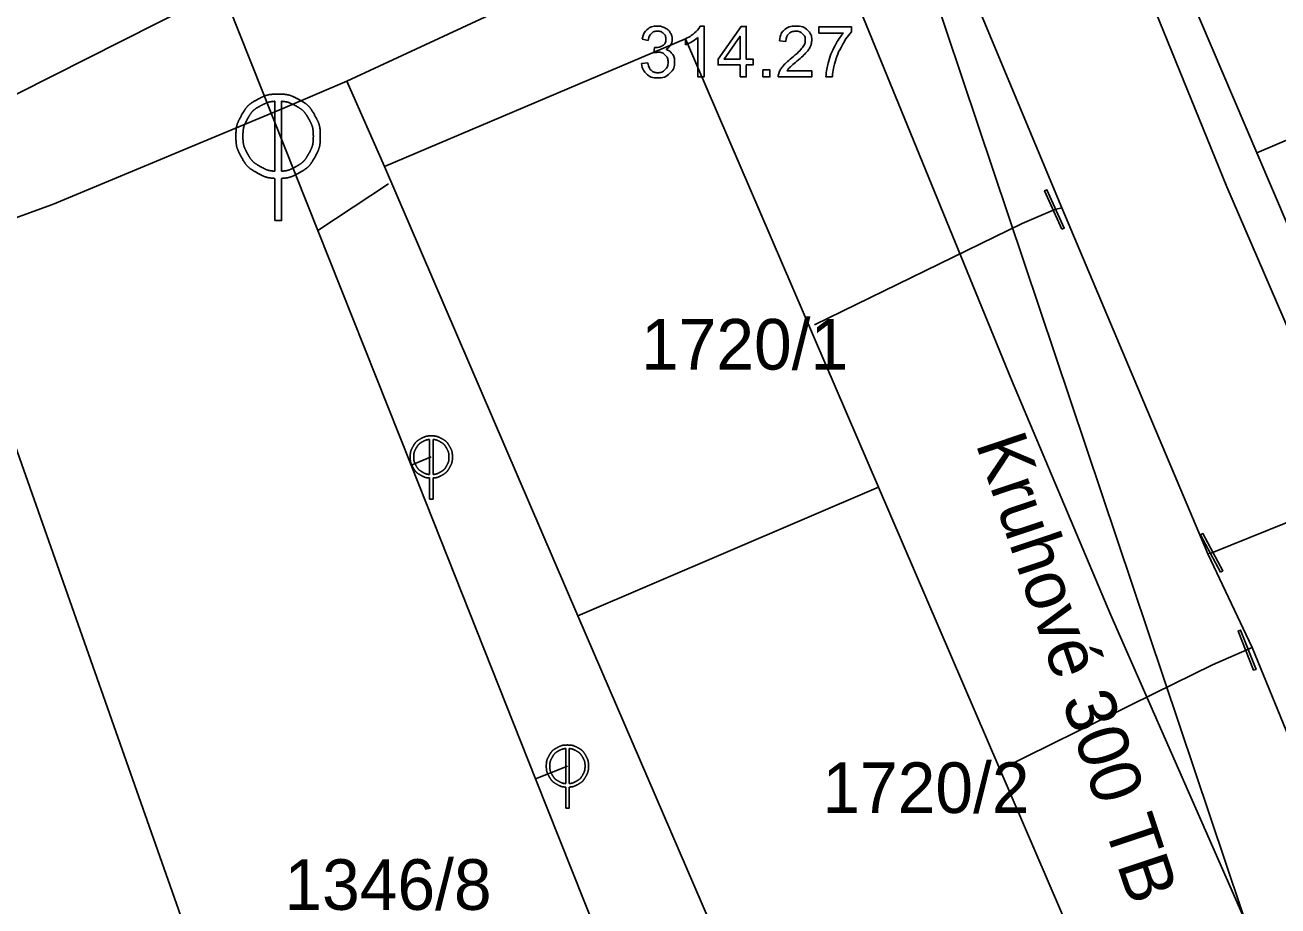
# Model space of a CAD drawing. Extents: x -562248 to -562040, y -1079385 to -1079027.
# Drawn here: x -562124.4 to -562087.3, y -1079242.75 to -1079216.65 of the extents above; entities that cross this region are included whole.
import ezdxf

# ---------------------------------------------------------------- set-up
doc = ezdxf.new("R2010")
doc.units = 0
for name, color, linetype in [('Armatura vodovodní', 7, 'Continuous'), ('Default', 7, 'Continuous'), ('Kanalizační přípojka', 7, 'Continuous'), ('Kanalizační stoka', 7, 'Continuous'), ('Kanalizační šachta', 7, 'Continuous'), ('Parcela-polygon', 7, 'Continuous'), ('Parcela-text', 7, 'Continuous'), ('Popis kmenové stoky', 7, 'Continuous'), ('Popis šachty', 7, 'Continuous'), ('Vodovodní přípojka', 7, 'Continuous'), ('Vodovodní řad', 7, 'Continuous')]:
    doc.layers.add(name, color=color, linetype=linetype)

msp = doc.modelspace()

# ---------------------------------------------------------------- linework, layer by layer
at = {"layer": 'Armatura vodovodní'}
for points in [[(-562093.697, -1079222.7), (-562093.626, -1079222.668), (-562094.14, -1079221.529), (-562094.211, -1079221.561)], [(-562088.996, -1079232.86), (-562088.927, -1079232.822), (-562089.519, -1079231.722), (-562089.588, -1079231.759)], [(-562088.018, -1079235.772), (-562087.946, -1079235.744), (-562088.405, -1079234.581), (-562088.478, -1079234.61)]]:
    msp.add_lwpolyline(points, close=True, dxfattribs=at)
at = {"layer": 'Default'}
for points in [[(-562116.907, -1079218.696), (-562117.118, -1079218.696), (-562117.323, -1079218.75), (-562117.522, -1079218.857)], [(-562116.293, -1079218.857), (-562116.492, -1079218.75), (-562116.697, -1079218.696), (-562116.907, -1079218.696)], [(-562117.522, -1079218.857), (-562117.72, -1079218.965), (-562117.876, -1079219.119), (-562117.988, -1079219.319)], [(-562117.81, -1079219.425), (-562117.717, -1079219.258), (-562117.588, -1079219.13), (-562117.422, -1079219.041)], [(-562117.422, -1079219.041), (-562117.278, -1079218.964), (-562117.141, -1079218.92), (-562117.009, -1079218.909)], [(-562116.804, -1079218.909), (-562116.672, -1079218.92), (-562116.535, -1079218.964), (-562116.394, -1079219.041)], [(-562116.394, -1079219.041), (-562116.228, -1079219.13), (-562116.098, -1079219.258), (-562116.004, -1079219.425)], [(-562115.825, -1079219.319), (-562115.937, -1079219.119), (-562116.093, -1079218.965), (-562116.293, -1079218.857)], [(-562117.988, -1079219.319), (-562118.1, -1079219.519), (-562118.157, -1079219.728), (-562118.157, -1079219.946)], [(-562117.949, -1079219.946), (-562117.949, -1079219.766), (-562117.903, -1079219.592), (-562117.81, -1079219.425)], [(-562116.004, -1079219.425), (-562115.911, -1079219.592), (-562115.864, -1079219.766), (-562115.864, -1079219.946)], [(-562115.657, -1079219.946), (-562115.657, -1079219.728), (-562115.713, -1079219.519), (-562115.825, -1079219.319)], [(-562118.157, -1079219.946), (-562118.157, -1079220.163), (-562118.102, -1079220.37), (-562117.992, -1079220.569)], [(-562117.812, -1079220.464), (-562117.903, -1079220.299), (-562117.949, -1079220.127), (-562117.949, -1079219.946)], [(-562115.864, -1079219.946), (-562115.864, -1079220.127), (-562115.91, -1079220.299), (-562116.001, -1079220.464)], [(-562115.821, -1079220.569), (-562115.711, -1079220.37), (-562115.657, -1079220.163), (-562115.657, -1079219.946)], [(-562117.427, -1079220.847), (-562117.593, -1079220.756), (-562117.721, -1079220.628), (-562117.812, -1079220.464)], [(-562116.001, -1079220.464), (-562116.092, -1079220.628), (-562116.22, -1079220.756), (-562116.384, -1079220.847)], [(-562117.992, -1079220.569), (-562117.882, -1079220.767), (-562117.728, -1079220.921), (-562117.529, -1079221.03)], [(-562117.009, -1079220.981), (-562117.146, -1079220.972), (-562117.285, -1079220.927), (-562117.427, -1079220.847)], [(-562116.384, -1079220.847), (-562116.527, -1079220.927), (-562116.667, -1079220.972), (-562116.804, -1079220.981)], [(-562116.284, -1079221.03), (-562116.085, -1079220.921), (-562115.931, -1079220.767), (-562115.821, -1079220.569)], [(-562117.529, -1079221.03), (-562117.355, -1079221.128), (-562117.182, -1079221.182), (-562117.009, -1079221.194)], [(-562116.804, -1079221.194), (-562116.631, -1079221.182), (-562116.458, -1079221.128), (-562116.284, -1079221.03)], [(-562112.678, -1079228.906), (-562112.777, -1079228.959), (-562112.855, -1079229.036), (-562112.911, -1079229.136)], [(-562112.82, -1079229.189), (-562112.774, -1079229.106), (-562112.709, -1079229.041), (-562112.626, -1079228.996)], [(-562112.37, -1079228.825), (-562112.476, -1079228.825), (-562112.578, -1079228.852), (-562112.678, -1079228.906)], [(-562112.626, -1079228.996), (-562112.555, -1079228.958), (-562112.486, -1079228.936), (-562112.421, -1079228.93)], [(-562112.062, -1079228.906), (-562112.162, -1079228.852), (-562112.264, -1079228.825), (-562112.37, -1079228.825)], [(-562112.319, -1079228.93), (-562112.252, -1079228.936), (-562112.184, -1079228.958), (-562112.114, -1079228.996)], [(-562112.114, -1079228.996), (-562112.031, -1079229.041), (-562111.966, -1079229.106), (-562111.918, -1079229.189)], [(-562111.829, -1079229.136), (-562111.885, -1079229.036), (-562111.963, -1079228.959), (-562112.062, -1079228.906)], [(-562112.911, -1079229.136), (-562112.967, -1079229.236), (-562112.995, -1079229.341), (-562112.995, -1079229.45)], [(-562112.995, -1079229.45), (-562112.995, -1079229.557), (-562112.967, -1079229.661), (-562112.912, -1079229.76)], [(-562112.89, -1079229.45), (-562112.89, -1079229.359), (-562112.867, -1079229.272), (-562112.82, -1079229.189)], [(-562112.822, -1079229.708), (-562112.867, -1079229.625), (-562112.89, -1079229.54), (-562112.89, -1079229.45)], [(-562111.918, -1079229.189), (-562111.871, -1079229.272), (-562111.848, -1079229.359), (-562111.848, -1079229.45)], [(-562111.848, -1079229.45), (-562111.848, -1079229.54), (-562111.87, -1079229.625), (-562111.916, -1079229.708)], [(-562111.745, -1079229.45), (-562111.745, -1079229.341), (-562111.773, -1079229.236), (-562111.829, -1079229.136)], [(-562111.827, -1079229.76), (-562111.772, -1079229.661), (-562111.745, -1079229.557), (-562111.745, -1079229.45)], [(-562112.912, -1079229.76), (-562112.857, -1079229.859), (-562112.779, -1079229.937), (-562112.68, -1079229.992)], [(-562112.629, -1079229.899), (-562112.712, -1079229.854), (-562112.776, -1079229.79), (-562112.822, -1079229.708)], [(-562111.916, -1079229.708), (-562111.961, -1079229.79), (-562112.026, -1079229.854), (-562112.109, -1079229.899)], [(-562112.058, -1079229.992), (-562111.958, -1079229.937), (-562111.881, -1079229.859), (-562111.827, -1079229.76)], [(-562112.68, -1079229.992), (-562112.594, -1079230.041), (-562112.508, -1079230.068), (-562112.421, -1079230.073)], [(-562112.421, -1079229.968), (-562112.49, -1079229.963), (-562112.559, -1079229.94), (-562112.629, -1079229.899)], [(-562112.109, -1079229.899), (-562112.18, -1079229.94), (-562112.25, -1079229.963), (-562112.319, -1079229.968)], [(-562112.319, -1079230.073), (-562112.232, -1079230.068), (-562112.145, -1079230.041), (-562112.058, -1079229.992)], [(-562108.34, -1079237.985), (-562108.446, -1079237.985), (-562108.548, -1079238.012), (-562108.648, -1079238.066)], [(-562108.032, -1079238.066), (-562108.132, -1079238.012), (-562108.234, -1079237.985), (-562108.34, -1079237.985)], [(-562108.881, -1079238.296), (-562108.937, -1079238.396), (-562108.965, -1079238.501), (-562108.965, -1079238.61)], [(-562108.648, -1079238.066), (-562108.747, -1079238.119), (-562108.825, -1079238.196), (-562108.881, -1079238.296)], [(-562108.86, -1079238.61), (-562108.86, -1079238.519), (-562108.837, -1079238.432), (-562108.79, -1079238.349)], [(-562108.79, -1079238.349), (-562108.744, -1079238.266), (-562108.679, -1079238.201), (-562108.596, -1079238.156)], [(-562108.596, -1079238.156), (-562108.525, -1079238.118), (-562108.456, -1079238.096), (-562108.391, -1079238.09)], [(-562108.289, -1079238.09), (-562108.222, -1079238.096), (-562108.154, -1079238.118), (-562108.084, -1079238.156)], [(-562108.084, -1079238.156), (-562108.001, -1079238.201), (-562107.936, -1079238.266), (-562107.888, -1079238.349)], [(-562107.799, -1079238.296), (-562107.855, -1079238.196), (-562107.933, -1079238.119), (-562108.032, -1079238.066)], [(-562107.888, -1079238.349), (-562107.841, -1079238.432), (-562107.818, -1079238.519), (-562107.818, -1079238.61)], [(-562107.715, -1079238.61), (-562107.715, -1079238.501), (-562107.743, -1079238.396), (-562107.799, -1079238.296)], [(-562108.965, -1079238.61), (-562108.965, -1079238.717), (-562108.937, -1079238.821), (-562108.882, -1079238.92)], [(-562108.792, -1079238.868), (-562108.837, -1079238.785), (-562108.86, -1079238.7), (-562108.86, -1079238.61)], [(-562107.818, -1079238.61), (-562107.818, -1079238.7), (-562107.84, -1079238.785), (-562107.886, -1079238.868)], [(-562107.797, -1079238.92), (-562107.742, -1079238.821), (-562107.715, -1079238.717), (-562107.715, -1079238.61)], [(-562108.882, -1079238.92), (-562108.827, -1079239.019), (-562108.749, -1079239.097), (-562108.65, -1079239.152)], [(-562108.599, -1079239.059), (-562108.682, -1079239.014), (-562108.746, -1079238.95), (-562108.792, -1079238.868)], [(-562108.391, -1079239.128), (-562108.46, -1079239.123), (-562108.529, -1079239.1), (-562108.599, -1079239.059)], [(-562108.079, -1079239.059), (-562108.15, -1079239.1), (-562108.22, -1079239.123), (-562108.289, -1079239.128)], [(-562107.886, -1079238.868), (-562107.931, -1079238.95), (-562107.996, -1079239.014), (-562108.079, -1079239.059)], [(-562108.027, -1079239.152), (-562107.928, -1079239.097), (-562107.851, -1079239.019), (-562107.797, -1079238.92)], [(-562108.65, -1079239.152), (-562108.564, -1079239.201), (-562108.478, -1079239.228), (-562108.391, -1079239.233)], [(-562108.289, -1079239.233), (-562108.202, -1079239.228), (-562108.115, -1079239.201), (-562108.027, -1079239.152)]]:
    msp.add_open_spline(points, degree=2, dxfattribs=at)
at = {"layer": 'Kanalizační přípojka'}
for points in [[(-562083.85, -1079218.7), (-562087.922, -1079220.435)], [(-562113.64, -1079221.36), (-562115.729, -1079222.739)], [(-562112.37, -1079229.45), (-562112.971, -1079229.689)], [(-562108.34, -1079238.61), (-562109.28, -1079238.983)]]:
    msp.add_lwpolyline(points, dxfattribs=at)
at = {"layer": 'Kanalizační stoka'}
for points in [[(-562123.1, -1079204.19), (-562122.674, -1079205.263), (-562115.729, -1079222.739), (-562112.971, -1079229.689), (-562109.28, -1079238.983), (-562105.344, -1079248.892), (-562104.57, -1079250.84)], [(-562093.91, -1079206.39), (-562092.611, -1079209.439), (-562091.608, -1079211.792), (-562087.92, -1079220.44), (-562086.97, -1079222.68), (-562085.81, -1079225.4)], [(-562083.791, -1079256.552), (-562098.95, -1079211.35)]]:
    msp.add_lwpolyline(points, dxfattribs=at)
at = {"layer": 'Kanalizační šachta'}
for points in [[(-562117.009, -1079218.909), (-562117.009, -1079220.981)], [(-562116.804, -1079220.981), (-562116.804, -1079218.909)], [(-562117.009, -1079222.446), (-562116.804, -1079222.446), (-562116.804, -1079221.194)], [(-562117.009, -1079221.194), (-562117.009, -1079222.446)], [(-562112.421, -1079228.93), (-562112.421, -1079229.968)], [(-562112.319, -1079229.968), (-562112.319, -1079228.93)], [(-562112.421, -1079230.7), (-562112.319, -1079230.7), (-562112.319, -1079230.073)], [(-562112.421, -1079230.073), (-562112.421, -1079230.7)], [(-562108.391, -1079238.09), (-562108.391, -1079239.128)], [(-562108.289, -1079239.128), (-562108.289, -1079238.09)], [(-562108.391, -1079239.86), (-562108.289, -1079239.86), (-562108.289, -1079239.233)], [(-562108.391, -1079239.233), (-562108.391, -1079239.86)]]:
    msp.add_lwpolyline(points, dxfattribs=at)
at = {"layer": 'Parcela-polygon'}
for points in [[(-562074.7, -1079253.09), (-562081.96, -1079237.32), (-562088.81, -1079221.44), (-562094.66, -1079207.06), (-562098.96, -1079196.12), (-562103.67, -1079183.92), (-562101.64, -1079183.14), (-562108.26, -1079165.24), (-562109.03, -1079162.72), (-562110.57, -1079158.43), (-562113.13, -1079150.92), (-562115.47, -1079143.79), (-562118.94, -1079132.53), (-562120.22, -1079128.2), (-562121.94, -1079119.29), (-562122.55, -1079115.89), (-562122.79, -1079112.89), (-562122.92, -1079108.96), (-562122.69, -1079105.05), (-562122.05, -1079101.16)], [(-562151.942, -1079151.733), (-562130.14, -1079147.9), (-562127.71, -1079147.6), (-562125.7, -1079148.16), (-562124.14, -1079150.14), (-562117.83, -1079168.5), (-562112.9, -1079182.58), (-562107.01, -1079197.84), (-562106.5, -1079200.3), (-562100.28, -1079214.7), (-562095.19, -1079227.16), (-562092.25, -1079234.14), (-562087.93, -1079243.96)], [(-562081.378, -1079153.144), (-562109.03, -1079162.72), (-562108.26, -1079165.24), (-562101.64, -1079183.14), (-562103.67, -1079183.92), (-562098.96, -1079196.12), (-562094.66, -1079207.06), (-562088.81, -1079221.44), (-562081.96, -1079237.32), (-562074.7, -1079253.09), (-562050.734, -1079242.89)], [(-562126.807, -1079223.131), (-562123.59, -1079221.97), (-562116.77, -1079219.12), (-562114.87, -1079218.31), (-562105.74, -1079214.07), (-562105.166, -1079213.728), (-562104.544, -1079213.484), (-562103.89, -1079213.344), (-562103.223, -1079213.312), (-562102.559, -1079213.388), (-562101.916, -1079213.572), (-562101.311, -1079213.857), (-562100.761, -1079214.236), (-562100.28, -1079214.7), (-562106.5, -1079200.3), (-562106.547, -1079201.097), (-562106.734, -1079201.874), (-562107.054, -1079202.606), (-562107.496, -1079203.271), (-562108.049, -1079203.848), (-562108.694, -1079204.319), (-562109.412, -1079204.67), (-562110.18, -1079204.89), (-562126.56, -1079212.06)], [(-562093.4, -1079243.66), (-562099.13, -1079230.34), (-562104.84, -1079217.06), (-562113.76, -1079220.84), (-562114.87, -1079218.31), (-562105.74, -1079214.07), (-562105.166, -1079213.728), (-562104.544, -1079213.484), (-562103.89, -1079213.344), (-562103.223, -1079213.312), (-562102.559, -1079213.388), (-562101.916, -1079213.572), (-562101.311, -1079213.857), (-562100.761, -1079214.236), (-562100.28, -1079214.7), (-562095.19, -1079227.16), (-562092.25, -1079234.14), (-562087.93, -1079243.96)], [(-562125.839, -1079250.062), (-562115.46, -1079274.84), (-562111.34, -1079272.6), (-562115.82, -1079264.13), (-562111.86, -1079261.96), (-562112.48, -1079260.84), (-562109.81, -1079259.38), (-562109.2, -1079260.5), (-562101.14, -1079256.08), (-562102.73, -1079253.17), (-562100.18, -1079251.98), (-562102.28, -1079247.51), (-562108.03, -1079234.16), (-562113.76, -1079220.84), (-562114.87, -1079218.31), (-562116.77, -1079219.12), (-562123.59, -1079221.97), (-562126.807, -1079223.131)], [(-562126.807, -1079223.131), (-562118.618, -1079246.395), (-562125.839, -1079250.062)]]:
    msp.add_lwpolyline(points, dxfattribs=at)
for points in [[(-562113.76, -1079220.84), (-562104.84, -1079217.06), (-562099.13, -1079230.34), (-562108.03, -1079234.16)], [(-562099.13, -1079230.34), (-562093.4, -1079243.66), (-562102.28, -1079247.51), (-562108.03, -1079234.16)]]:
    msp.add_lwpolyline(points, close=True, dxfattribs=at)
at = {"layer": 'Popis šachty'}
for points in [[(-562104.409, -1079216.683), (-562104.29, -1079216.683), (-562104.29, -1079218.189)], [(-562103.228, -1079218.189), (-562103.228, -1079217.83), (-562103.879, -1079217.83), (-562103.879, -1079217.661), (-562103.195, -1079216.689), (-562103.044, -1079216.689), (-562103.044, -1079217.661), (-562102.842, -1079217.661), (-562102.842, -1079217.83), (-562103.044, -1079217.83), (-562103.044, -1079218.189), (-562103.228, -1079218.189)], [(-562100.893, -1079216.886), (-562100.893, -1079216.708), (-562099.923, -1079216.708), (-562099.923, -1079216.852)], [(-562105.945, -1079217.105), (-562106.129, -1079217.072)], [(-562104.842, -1079217.238), (-562104.842, -1079217.06)], [(-562104.29, -1079218.189), (-562104.474, -1079218.189), (-562104.474, -1079217.016)], [(-562103.228, -1079217.661), (-562103.228, -1079216.984), (-562103.698, -1079217.661), (-562103.228, -1079217.661)], [(-562101.871, -1079217.136), (-562102.061, -1079217.117)], [(-562100.159, -1079216.886), (-562100.893, -1079216.886)], [(-562105.784, -1079217.478), (-562105.763, -1079217.317)], [(-562106.147, -1079217.791), (-562105.963, -1079217.767)], [(-562102.55, -1079218.189), (-562102.55, -1079217.98), (-562102.341, -1079217.98), (-562102.341, -1079218.189), (-562102.55, -1079218.189)], [(-562101.104, -1079218.012), (-562101.104, -1079218.189), (-562102.095, -1079218.189)], [(-562101.839, -1079218.012), (-562101.104, -1079218.012)], [(-562100.494, -1079218.189), (-562100.684, -1079218.189)]]:
    msp.add_lwpolyline(points, dxfattribs=at)
for points in [[(-562106.129, -1079217.072), (-562106.095, -1079216.887), (-562105.975, -1079216.785), (-562105.855, -1079216.683), (-562105.677, -1079216.683), (-562105.554, -1079216.683), (-562105.451, -1079216.736), (-562105.348, -1079216.789), (-562105.293, -1079216.879), (-562105.238, -1079216.97), (-562105.238, -1079217.072), (-562105.238, -1079217.17), (-562105.29, -1079217.249), (-562105.342, -1079217.329), (-562105.445, -1079217.376), (-562105.312, -1079217.407), (-562105.238, -1079217.503), (-562105.165, -1079217.6), (-562105.165, -1079217.745), (-562105.165, -1079217.941), (-562105.308, -1079218.078), (-562105.451, -1079218.214), (-562105.67, -1079218.214), (-562105.868, -1079218.214), (-562105.998, -1079218.096), (-562106.128, -1079217.979), (-562106.147, -1079217.791)], [(-562105.763, -1079217.317), (-562105.745, -1079217.319), (-562105.734, -1079217.319), (-562105.616, -1079217.319), (-562105.522, -1079217.257), (-562105.428, -1079217.196), (-562105.428, -1079217.068), (-562105.428, -1079216.967), (-562105.496, -1079216.901), (-562105.565, -1079216.834), (-562105.673, -1079216.834), (-562105.781, -1079216.834), (-562105.852, -1079216.902), (-562105.924, -1079216.97), (-562105.945, -1079217.105)], [(-562104.842, -1079217.06), (-562104.688, -1079216.987), (-562104.572, -1079216.884), (-562104.457, -1079216.78), (-562104.409, -1079216.683)], [(-562102.095, -1079218.189), (-562102.097, -1079218.122), (-562102.074, -1079218.061), (-562102.036, -1079217.96), (-562101.952, -1079217.861), (-562101.869, -1079217.763), (-562101.711, -1079217.635), (-562101.467, -1079217.434), (-562101.382, -1079217.317), (-562101.296, -1079217.2), (-562101.296, -1079217.095), (-562101.296, -1079216.986), (-562101.374, -1079216.91), (-562101.452, -1079216.835), (-562101.578, -1079216.835), (-562101.711, -1079216.835), (-562101.79, -1079216.915), (-562101.87, -1079216.995), (-562101.871, -1079217.136)], [(-562102.061, -1079217.117), (-562102.041, -1079216.905), (-562101.914, -1079216.794), (-562101.788, -1079216.683), (-562101.574, -1079216.683), (-562101.358, -1079216.683), (-562101.232, -1079216.803), (-562101.106, -1079216.923), (-562101.106, -1079217.099), (-562101.106, -1079217.189), (-562101.143, -1079217.276), (-562101.18, -1079217.363), (-562101.265, -1079217.459), (-562101.35, -1079217.556), (-562101.549, -1079217.723), (-562101.714, -1079217.862), (-562101.761, -1079217.912), (-562101.808, -1079217.962), (-562101.839, -1079218.012)], [(-562099.923, -1079216.852), (-562100.066, -1079217.004), (-562100.207, -1079217.257), (-562100.347, -1079217.51), (-562100.424, -1079217.777), (-562100.479, -1079217.965), (-562100.494, -1079218.189)], [(-562104.474, -1079217.016), (-562104.541, -1079217.079), (-562104.649, -1079217.143), (-562104.756, -1079217.206), (-562104.842, -1079217.238)], [(-562100.684, -1079218.189), (-562100.681, -1079218.012), (-562100.615, -1079217.761), (-562100.548, -1079217.511), (-562100.424, -1079217.278), (-562100.3, -1079217.045), (-562100.159, -1079216.886)], [(-562105.963, -1079217.767), (-562105.931, -1079217.924), (-562105.855, -1079217.993), (-562105.779, -1079218.062), (-562105.669, -1079218.062), (-562105.539, -1079218.062), (-562105.45, -1079217.972), (-562105.36, -1079217.882), (-562105.36, -1079217.749), (-562105.36, -1079217.622), (-562105.443, -1079217.54), (-562105.526, -1079217.457), (-562105.654, -1079217.457), (-562105.706, -1079217.457), (-562105.784, -1079217.478)]]:
    msp.add_open_spline(points, degree=3, dxfattribs=at)
at = {"layer": 'Vodovodní přípojka'}
for points in [[(-562093.695, -1079222.062), (-562093.901, -1079222.115), (-562094.869, -1079222.536), (-562101.024, -1079225.537)], [(-562089.377, -1079232.32), (-562089.258, -1079232.291), (-562084.807, -1079230.492), (-562078.287, -1079227.545)], [(-562088.062, -1079235.093), (-562089.236, -1079235.609), (-562090.964, -1079236.462), (-562095.527, -1079238.715)]]:
    msp.add_lwpolyline(points, dxfattribs=at)
at = {"layer": 'Vodovodní řad'}
for points in [[(-562093.695, -1079222.062), (-562096.777, -1079214.665), (-562098.046, -1079211.694)], [(-562127.816, -1079220.267), (-562127.696, -1079220.234), (-562119.47, -1079216.08)], [(-562076.873, -1079261.222), (-562077.411, -1079260.349), (-562080.838, -1079252.747), (-562088.062, -1079235.093), (-562089.377, -1079232.32), (-562093.695, -1079222.062)]]:
    msp.add_lwpolyline(points, dxfattribs=at)

# ---------------------------------------------------------------- texts
at = {"layer": 'Parcela-text'}
for s, p in [('1720/1', (-562106.16, -1079226.86)), ('1720/2', (-562100.79, -1079240)), ('1346/8', (-562116.72, -1079242.87))]:
    msp.add_text(s, height=1.5, dxfattribs=at).set_placement(p)
at = {"layer": 'Popis kmenové stoky'}
msp.add_text('Kruhové 300 TB', height=1.5, rotation=288.5395, dxfattribs=at).set_placement((-562096.259, -1079229.048))

doc.saveas('drawing.dxf')
